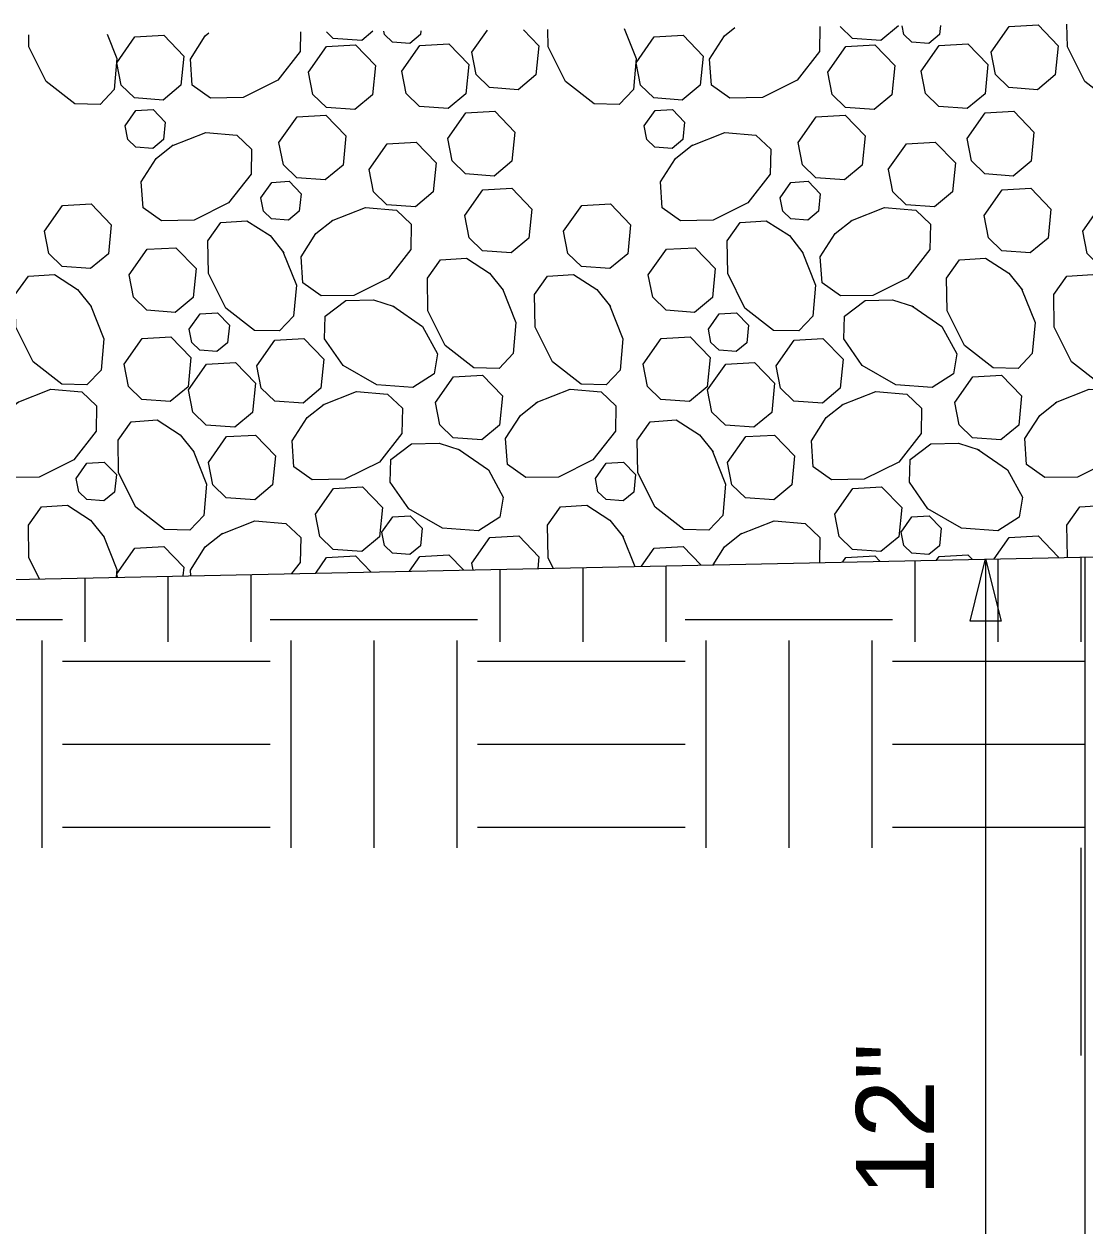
# Model space of a CAD drawing. Extents: x 10368.3 to 10426.8, y 9886.2 to 9938.1.
# Drawn here: x 10376.31 to 10390.52, y 9908.51 to 9924.61 of the extents above; entities that cross this region are included whole.
import ezdxf

# ---------------------------------------------------------------- set-up
doc = ezdxf.new("R2010")
doc.units = 0
for name, color, linetype in [('Default', 7, 'Continuous'), ('G-ANNO-TEXT', 7, 'Continuous'), ('G-DETL-OTLN', 7, 'Continuous'), ('G-DETL-PATT', 7, 'Continuous')]:
    doc.layers.add(name, color=color, linetype=linetype)

# ---------------------------------------------------------------- blocks, each defined once
blk = doc.blocks.new('TERARR')
at = {"layer": 'Default'}
blk.add_lwpolyline([(-0.667, 0.167), (0, 0), (-0.667, -0.167)], close=True, dxfattribs=at)

msp = doc.modelspace()

# ---------------------------------------------------------------- linework, layer by layer
at = {"layer": 'Default'}
for p, q in [((10389.352, 9917.445), (10389.352, 9916.333)), ((10390.464, 9917.469), (10390.464, 9916.333)), ((10390.464, 9913.573), (10390.464, 9910.793))]:
    msp.add_line(p, q, dxfattribs=at)
for points in [[(10388.022, 9924.584), (10387.785, 9924.387), (10387.404, 9924.414), (10387.237, 9924.576)], [(10388.583, 9924.59), (10388.57, 9924.466), (10388.427, 9924.347), (10388.198, 9924.363), (10388.09, 9924.468), (10388.068, 9924.585)], [(10380.98, 9924.511), (10380.831, 9924.387), (10380.449, 9924.414), (10380.357, 9924.504)], [(10381.621, 9924.518), (10381.616, 9924.466), (10381.473, 9924.347), (10381.244, 9924.363), (10381.136, 9924.468), (10381.127, 9924.512)], [(10377.56, 9917.198), (10377.551, 9917.245)]]:
    msp.add_lwpolyline(points, dxfattribs=at)
at = {"layer": 'G-ANNO-TEXT'}
msp.add_line((10389.187, 9917.408), (10389.187, 9902.473), dxfattribs=at)
at = {"layer": 'G-DETL-OTLN'}
for p, q in [((10368.322, 9917.004), (10418.193, 9918.051)), ((10390.518, 9917.47), (10390.518, 9903.473))]:
    msp.add_line(p, q, dxfattribs=at)
at = {"layer": 'G-DETL-PATT'}
for p, q in [((10383.793, 9917.329), (10383.793, 9916.333)), ((10384.905, 9917.352), (10384.905, 9916.333)), ((10388.24, 9917.422), (10388.24, 9916.333)), ((10377.122, 9917.189), (10377.122, 9916.333)), ((10378.233, 9917.212), (10378.233, 9916.333)), ((10379.345, 9917.235), (10379.345, 9916.333)), ((10382.681, 9917.305), (10382.681, 9916.333)), ((10374.043, 9916.63), (10376.823, 9916.63)), ((10379.603, 9916.63), (10382.382, 9916.63)), ((10385.162, 9916.63), (10387.942, 9916.63)), ((10376.545, 9916.352), (10376.545, 9913.573)), ((10379.881, 9916.352), (10379.881, 9913.573)), ((10380.993, 9916.352), (10380.993, 9913.573)), ((10382.104, 9916.352), (10382.104, 9913.573)), ((10385.44, 9916.352), (10385.44, 9913.573)), ((10386.552, 9916.352), (10386.552, 9913.573)), ((10387.664, 9916.352), (10387.664, 9913.573)), ((10376.823, 9916.074), (10379.603, 9916.074)), ((10382.382, 9916.074), (10385.162, 9916.074)), ((10387.942, 9916.074), (10390.518, 9916.074)), ((10376.823, 9914.963), (10379.603, 9914.963)), ((10382.382, 9914.963), (10385.162, 9914.963)), ((10387.942, 9914.963), (10390.518, 9914.963)), ((10376.823, 9913.851), (10379.603, 9913.851)), ((10382.382, 9913.851), (10385.162, 9913.851)), ((10387.942, 9913.851), (10390.518, 9913.851))]:
    msp.add_line(p, q, dxfattribs=at)
for points in [[(10386.967, 9924.573), (10386.961, 9924.239), (10386.661, 9923.856), (10386.197, 9923.624), (10385.76, 9923.616), (10385.514, 9923.791), (10385.491, 9924.139), (10385.691, 9924.45), (10385.83, 9924.561)], [(10389.261, 9924.229), (10389.503, 9924.574), (10389.889, 9924.596), (10390.158, 9924.317), (10390.119, 9923.927), (10389.88, 9923.728), (10389.499, 9923.756), (10389.319, 9923.93), (10389.261, 9924.229)], [(10391.28, 9924.598), (10391.459, 9924.145), (10391.423, 9923.729), (10391.235, 9923.532), (10390.898, 9923.538), (10390.514, 9923.838), (10390.283, 9924.302), (10390.277, 9924.608)], [(10377.42, 9924.474), (10377.551, 9924.145), (10377.515, 9923.729), (10377.327, 9923.532), (10376.989, 9923.538), (10376.606, 9923.838), (10376.374, 9924.302), (10376.371, 9924.463)], [(10377.551, 9924.09), (10377.793, 9924.435), (10378.179, 9924.457), (10378.448, 9924.178), (10378.409, 9923.788), (10378.17, 9923.589), (10377.789, 9923.617), (10377.609, 9923.791), (10377.551, 9924.09)], [(10380.011, 9924.501), (10380.006, 9924.239), (10379.706, 9923.856), (10379.243, 9923.624), (10378.806, 9923.616), (10378.56, 9923.791), (10378.537, 9924.139), (10378.736, 9924.45), (10378.784, 9924.488)], [(10382.306, 9924.229), (10382.515, 9924.527)], [(10382.996, 9924.532), (10383.203, 9924.317), (10383.165, 9923.927), (10382.926, 9923.728), (10382.544, 9923.756), (10382.365, 9923.93), (10382.307, 9924.229)], [(10384.346, 9924.546), (10384.505, 9924.145), (10384.469, 9923.729), (10384.281, 9923.532), (10383.944, 9923.538), (10383.56, 9923.838), (10383.328, 9924.302), (10383.324, 9924.535)], [(10384.505, 9924.09), (10384.747, 9924.435), (10385.134, 9924.457), (10385.402, 9924.178), (10385.363, 9923.788), (10385.125, 9923.589), (10384.743, 9923.617), (10384.564, 9923.791), (10384.505, 9924.09)], [(10380.119, 9923.963), (10380.361, 9924.307), (10380.748, 9924.329), (10381.016, 9924.051), (10380.977, 9923.66), (10380.739, 9923.462), (10380.357, 9923.489), (10380.177, 9923.663), (10380.119, 9923.962)], [(10381.368, 9923.977), (10381.61, 9924.321), (10381.996, 9924.343), (10382.265, 9924.065), (10382.226, 9923.674), (10381.987, 9923.476), (10381.606, 9923.503), (10381.426, 9923.678), (10381.368, 9923.977)], [(10387.073, 9923.963), (10387.315, 9924.307), (10387.702, 9924.329), (10387.97, 9924.051), (10387.932, 9923.66), (10387.693, 9923.462), (10387.311, 9923.489), (10387.132, 9923.663), (10387.074, 9923.962)], [(10388.322, 9923.977), (10388.564, 9924.321), (10388.951, 9924.343), (10389.219, 9924.065), (10389.18, 9923.674), (10388.942, 9923.476), (10388.56, 9923.503), (10388.38, 9923.678), (10388.322, 9923.977)], [(10377.661, 9923.242), (10377.806, 9923.448), (10378.038, 9923.462), (10378.199, 9923.295), (10378.176, 9923.06), (10378.033, 9922.941), (10377.804, 9922.958), (10377.696, 9923.062), (10377.661, 9923.242)], [(10381.984, 9923.073), (10382.226, 9923.417), (10382.612, 9923.439), (10382.881, 9923.161), (10382.842, 9922.771), (10382.603, 9922.572), (10382.222, 9922.6), (10382.042, 9922.774), (10381.984, 9923.073)], [(10384.615, 9923.242), (10384.761, 9923.448), (10384.992, 9923.462), (10385.154, 9923.295), (10385.13, 9923.06), (10384.987, 9922.941), (10384.758, 9922.958), (10384.65, 9923.062), (10384.616, 9923.242)], [(10388.938, 9923.073), (10389.18, 9923.417), (10389.566, 9923.439), (10389.835, 9923.161), (10389.796, 9922.771), (10389.557, 9922.572), (10389.176, 9922.6), (10388.996, 9922.774), (10388.938, 9923.073)], [(10379.722, 9923.021), (10379.964, 9923.365), (10380.35, 9923.387), (10380.619, 9923.109), (10380.58, 9922.718), (10380.342, 9922.52), (10379.96, 9922.548), (10379.781, 9922.722), (10379.722, 9923.021)], [(10386.676, 9923.021), (10386.918, 9923.365), (10387.305, 9923.387), (10387.574, 9923.109), (10387.535, 9922.718), (10387.296, 9922.52), (10386.914, 9922.548), (10386.735, 9922.722), (10386.677, 9923.021)], [(10378.288, 9922.977), (10378.741, 9923.156), (10379.157, 9923.12), (10379.355, 9922.932), (10379.348, 9922.595), (10379.048, 9922.211), (10378.585, 9921.979), (10378.148, 9921.972), (10377.902, 9922.147), (10377.878, 9922.495), (10378.078, 9922.806), (10378.307, 9922.988)], [(10385.243, 9922.977), (10385.695, 9923.156), (10386.111, 9923.12), (10386.309, 9922.932), (10386.303, 9922.595), (10386.002, 9922.211), (10385.539, 9921.979), (10385.102, 9921.972), (10384.856, 9922.147), (10384.833, 9922.495), (10385.032, 9922.806), (10385.261, 9922.988)], [(10380.93, 9922.661), (10381.172, 9923.005), (10381.559, 9923.027), (10381.827, 9922.748), (10381.788, 9922.358), (10381.55, 9922.16), (10381.168, 9922.187), (10380.989, 9922.361), (10380.93, 9922.661)], [(10387.884, 9922.661), (10388.126, 9923.005), (10388.513, 9923.027), (10388.782, 9922.748), (10388.743, 9922.358), (10388.504, 9922.16), (10388.122, 9922.187), (10387.943, 9922.361), (10387.885, 9922.661)], [(10379.48, 9922.281), (10379.625, 9922.487), (10379.857, 9922.501), (10380.018, 9922.333), (10379.995, 9922.099), (10379.852, 9921.98), (10379.623, 9921.997), (10379.515, 9922.101), (10379.48, 9922.281)], [(10386.434, 9922.281), (10386.579, 9922.487), (10386.811, 9922.501), (10386.972, 9922.333), (10386.949, 9922.099), (10386.806, 9921.98), (10386.577, 9921.997), (10386.469, 9922.101), (10386.434, 9922.281)], [(10382.211, 9922.042), (10382.453, 9922.387), (10382.84, 9922.409), (10383.108, 9922.13), (10383.07, 9921.74), (10382.831, 9921.541), (10382.449, 9921.569), (10382.27, 9921.743), (10382.212, 9922.042)], [(10389.166, 9922.042), (10389.408, 9922.387), (10389.794, 9922.409), (10390.063, 9922.13), (10390.024, 9921.74), (10389.785, 9921.541), (10389.404, 9921.569), (10389.224, 9921.743), (10389.166, 9922.042)], [(10376.58, 9921.832), (10376.822, 9922.176), (10377.209, 9922.198), (10377.477, 9921.919), (10377.438, 9921.529), (10377.2, 9921.331), (10376.818, 9921.358), (10376.639, 9921.532), (10376.581, 9921.831)], [(10380.428, 9921.971), (10380.881, 9922.15), (10381.297, 9922.114), (10381.494, 9921.926), (10381.488, 9921.589), (10381.188, 9921.205), (10380.724, 9920.973), (10380.287, 9920.966), (10380.041, 9921.141), (10380.018, 9921.489), (10380.218, 9921.8), (10380.446, 9921.982)], [(10383.535, 9921.832), (10383.777, 9922.176), (10384.163, 9922.198), (10384.432, 9921.919), (10384.393, 9921.529), (10384.154, 9921.331), (10383.773, 9921.358), (10383.593, 9921.532), (10383.535, 9921.831)], [(10387.382, 9921.971), (10387.835, 9922.15), (10388.251, 9922.114), (10388.449, 9921.926), (10388.442, 9921.589), (10388.142, 9921.205), (10387.678, 9920.973), (10387.242, 9920.966), (10386.996, 9921.141), (10386.972, 9921.489), (10387.172, 9921.8), (10387.401, 9921.982)], [(10390.489, 9921.832), (10390.731, 9922.176), (10391.117, 9922.198), (10391.386, 9921.919), (10391.347, 9921.529), (10391.108, 9921.331), (10390.727, 9921.358), (10390.547, 9921.532), (10390.489, 9921.831)], [(10379.775, 9921.563), (10379.955, 9921.11), (10379.919, 9920.694), (10379.731, 9920.497), (10379.393, 9920.503), (10379.01, 9920.803), (10378.778, 9921.267), (10378.77, 9921.704), (10378.945, 9921.95), (10379.293, 9921.973), (10379.605, 9921.773), (10379.787, 9921.545)], [(10386.73, 9921.563), (10386.909, 9921.11), (10386.873, 9920.694), (10386.685, 9920.497), (10386.348, 9920.503), (10385.964, 9920.803), (10385.733, 9921.267), (10385.725, 9921.704), (10385.9, 9921.95), (10386.248, 9921.973), (10386.559, 9921.773), (10386.741, 9921.545)], [(10377.715, 9921.246), (10377.957, 9921.59), (10378.343, 9921.612), (10378.612, 9921.334), (10378.573, 9920.944), (10378.334, 9920.745), (10377.953, 9920.773), (10377.773, 9920.947), (10377.715, 9921.246)], [(10384.669, 9921.246), (10384.911, 9921.59), (10385.297, 9921.612), (10385.566, 9921.334), (10385.527, 9920.944), (10385.289, 9920.745), (10384.907, 9920.773), (10384.728, 9920.947), (10384.669, 9921.246)], [(10382.715, 9921.062), (10382.895, 9920.609), (10382.859, 9920.193), (10382.671, 9919.995), (10382.333, 9920.002), (10381.95, 9920.302), (10381.718, 9920.765), (10381.71, 9921.202), (10381.885, 9921.448), (10382.233, 9921.471), (10382.544, 9921.272), (10382.727, 9921.043)], [(10389.669, 9921.062), (10389.849, 9920.609), (10389.813, 9920.193), (10389.625, 9919.995), (10389.287, 9920.002), (10388.904, 9920.302), (10388.672, 9920.765), (10388.664, 9921.202), (10388.839, 9921.448), (10389.187, 9921.471), (10389.499, 9921.272), (10389.681, 9921.043)], [(10377.196, 9920.842), (10377.375, 9920.389), (10377.339, 9919.973), (10377.151, 9919.776), (10376.814, 9919.782), (10376.43, 9920.082), (10376.199, 9920.546), (10376.191, 9920.983), (10376.366, 9921.229), (10376.714, 9921.252), (10377.025, 9921.052), (10377.207, 9920.824)], [(10384.15, 9920.842), (10384.329, 9920.389), (10384.294, 9919.973), (10384.106, 9919.776), (10383.768, 9919.782), (10383.385, 9920.082), (10383.153, 9920.546), (10383.145, 9920.983), (10383.32, 9921.229), (10383.668, 9921.252), (10383.979, 9921.052), (10384.162, 9920.824)], [(10391.104, 9920.842), (10391.284, 9920.389), (10391.248, 9919.973), (10391.06, 9919.776), (10390.722, 9919.782), (10390.339, 9920.082), (10390.107, 9920.546), (10390.099, 9920.983), (10390.274, 9921.229), (10390.622, 9921.252), (10390.934, 9921.052), (10391.116, 9920.824)], [(10381.246, 9920.833), (10381.647, 9920.556), (10381.847, 9920.19), (10381.801, 9919.921), (10381.516, 9919.739), (10381.031, 9919.776), (10380.581, 9920.033), (10380.332, 9920.392), (10380.341, 9920.694), (10380.618, 9920.906), (10380.987, 9920.913), (10381.266, 9920.824)], [(10388.2, 9920.833), (10388.601, 9920.556), (10388.801, 9920.19), (10388.755, 9919.921), (10388.471, 9919.739), (10387.985, 9919.776), (10387.535, 9920.033), (10387.286, 9920.392), (10387.295, 9920.694), (10387.572, 9920.906), (10387.942, 9920.913), (10388.22, 9920.824)], [(10378.52, 9920.521), (10378.665, 9920.727), (10378.897, 9920.741), (10379.058, 9920.573), (10379.035, 9920.339), (10378.892, 9920.22), (10378.663, 9920.237), (10378.555, 9920.341), (10378.52, 9920.521)], [(10385.474, 9920.521), (10385.619, 9920.727), (10385.851, 9920.741), (10386.012, 9920.573), (10385.989, 9920.339), (10385.846, 9920.22), (10385.617, 9920.237), (10385.509, 9920.341), (10385.474, 9920.521)], [(10377.647, 9920.051), (10377.889, 9920.395), (10378.275, 9920.417), (10378.544, 9920.139), (10378.505, 9919.748), (10378.266, 9919.55), (10377.885, 9919.577), (10377.705, 9919.751), (10377.647, 9920.051)], [(10379.427, 9920.03), (10379.669, 9920.374), (10380.055, 9920.396), (10380.324, 9920.118), (10380.285, 9919.728), (10380.046, 9919.529), (10379.665, 9919.557), (10379.485, 9919.731), (10379.427, 9920.03)], [(10384.601, 9920.051), (10384.843, 9920.395), (10385.23, 9920.417), (10385.498, 9920.139), (10385.459, 9919.748), (10385.221, 9919.55), (10384.839, 9919.577), (10384.66, 9919.751), (10384.602, 9920.051)], [(10386.381, 9920.03), (10386.623, 9920.374), (10387.009, 9920.396), (10387.278, 9920.118), (10387.239, 9919.728), (10387.001, 9919.529), (10386.619, 9919.557), (10386.439, 9919.731), (10386.381, 9920.03)], [(10378.51, 9919.709), (10378.752, 9920.053), (10379.138, 9920.075), (10379.407, 9919.797), (10379.368, 9919.406), (10379.129, 9919.208), (10378.748, 9919.236), (10378.568, 9919.41), (10378.51, 9919.709)], [(10385.464, 9919.709), (10385.706, 9920.053), (10386.092, 9920.075), (10386.361, 9919.797), (10386.322, 9919.406), (10386.083, 9919.208), (10385.702, 9919.236), (10385.522, 9919.41), (10385.464, 9919.709)], [(10381.819, 9919.538), (10382.061, 9919.883), (10382.447, 9919.905), (10382.716, 9919.626), (10382.677, 9919.236), (10382.438, 9919.037), (10382.057, 9919.065), (10381.877, 9919.239), (10381.819, 9919.538)], [(10388.773, 9919.538), (10389.015, 9919.883), (10389.401, 9919.905), (10389.67, 9919.626), (10389.631, 9919.236), (10389.392, 9919.037), (10389.011, 9919.065), (10388.832, 9919.239), (10388.773, 9919.538)], [(10376.214, 9919.537), (10376.667, 9919.716), (10377.083, 9919.68), (10377.28, 9919.492), (10377.274, 9919.155), (10376.974, 9918.771), (10376.51, 9918.539), (10376.073, 9918.532), (10375.827, 9918.707), (10375.804, 9919.055), (10376.004, 9919.366), (10376.232, 9919.548)], [(10380.309, 9919.507), (10380.761, 9919.686), (10381.177, 9919.65), (10381.375, 9919.462), (10381.369, 9919.125), (10381.069, 9918.741), (10380.605, 9918.51), (10380.168, 9918.502), (10379.922, 9918.677), (10379.899, 9919.025), (10380.098, 9919.336), (10380.327, 9919.518)], [(10383.168, 9919.537), (10383.621, 9919.716), (10384.037, 9919.68), (10384.235, 9919.492), (10384.228, 9919.155), (10383.928, 9918.771), (10383.465, 9918.539), (10383.028, 9918.532), (10382.782, 9918.707), (10382.758, 9919.055), (10382.958, 9919.366), (10383.187, 9919.548)], [(10387.263, 9919.507), (10387.716, 9919.686), (10388.132, 9919.65), (10388.329, 9919.462), (10388.323, 9919.125), (10388.023, 9918.741), (10387.559, 9918.51), (10387.122, 9918.502), (10386.876, 9918.677), (10386.853, 9919.025), (10387.053, 9919.336), (10387.281, 9919.518)], [(10390.123, 9919.537), (10390.575, 9919.716), (10390.991, 9919.68), (10391.189, 9919.492), (10391.183, 9919.155), (10390.882, 9918.771), (10390.419, 9918.539), (10389.982, 9918.532), (10389.736, 9918.707), (10389.713, 9919.055), (10389.912, 9919.366), (10390.141, 9919.548)], [(10378.572, 9918.895), (10378.751, 9918.442), (10378.715, 9918.026), (10378.527, 9917.828), (10378.19, 9917.835), (10377.806, 9918.135), (10377.575, 9918.598), (10377.567, 9919.035), (10377.742, 9919.281), (10378.09, 9919.305), (10378.401, 9919.105), (10378.583, 9918.876)], [(10385.526, 9918.895), (10385.705, 9918.442), (10385.669, 9918.026), (10385.482, 9917.828), (10385.144, 9917.835), (10384.76, 9918.135), (10384.529, 9918.598), (10384.521, 9919.035), (10384.696, 9919.281), (10385.044, 9919.305), (10385.355, 9919.105), (10385.538, 9918.876)], [(10378.777, 9918.736), (10379.019, 9919.081), (10379.406, 9919.102), (10379.674, 9918.824), (10379.636, 9918.434), (10379.397, 9918.235), (10379.015, 9918.263), (10378.836, 9918.437), (10378.777, 9918.736)], [(10385.732, 9918.736), (10385.974, 9919.081), (10386.36, 9919.102), (10386.629, 9918.824), (10386.59, 9918.434), (10386.351, 9918.235), (10385.97, 9918.263), (10385.79, 9918.437), (10385.732, 9918.736)], [(10382.126, 9918.913), (10382.527, 9918.636), (10382.727, 9918.27), (10382.681, 9918.001), (10382.396, 9917.819), (10381.911, 9917.856), (10381.461, 9918.113), (10381.212, 9918.472), (10381.221, 9918.774), (10381.498, 9918.986), (10381.867, 9918.993), (10382.146, 9918.904)], [(10389.08, 9918.913), (10389.481, 9918.636), (10389.681, 9918.27), (10389.635, 9918.001), (10389.351, 9917.819), (10388.865, 9917.856), (10388.415, 9918.113), (10388.166, 9918.472), (10388.175, 9918.774), (10388.452, 9918.986), (10388.822, 9918.993), (10389.1, 9918.904)], [(10377.005, 9918.521), (10377.151, 9918.727), (10377.382, 9918.741), (10377.544, 9918.573), (10377.52, 9918.339), (10377.377, 9918.22), (10377.148, 9918.237), (10377.04, 9918.341), (10377.006, 9918.521)], [(10383.96, 9918.521), (10384.105, 9918.727), (10384.337, 9918.741), (10384.498, 9918.573), (10384.475, 9918.339), (10384.332, 9918.22), (10384.103, 9918.237), (10383.995, 9918.341), (10383.96, 9918.521)], [(10380.211, 9918.042), (10380.453, 9918.387), (10380.84, 9918.409), (10381.108, 9918.13), (10381.07, 9917.74), (10380.831, 9917.541), (10380.449, 9917.569), (10380.27, 9917.743), (10380.212, 9918.042)], [(10387.166, 9918.042), (10387.408, 9918.387), (10387.794, 9918.409), (10388.063, 9918.13), (10388.024, 9917.74), (10387.785, 9917.541), (10387.404, 9917.569), (10387.224, 9917.743), (10387.166, 9918.042)], [(10376.514, 9917.176), (10376.374, 9917.456), (10376.366, 9917.893), (10376.541, 9918.139), (10376.889, 9918.163), (10377.2, 9917.963), (10377.383, 9917.734)], [(10383.396, 9917.32), (10383.328, 9917.456), (10383.321, 9917.893), (10383.495, 9918.139), (10383.844, 9918.163), (10384.155, 9917.963), (10384.337, 9917.734)], [(10390.282, 9917.465), (10390.275, 9917.893), (10390.45, 9918.139), (10390.798, 9918.163), (10391.109, 9917.963), (10391.291, 9917.734)], [(10378.946, 9917.776), (10379.399, 9917.955), (10379.815, 9917.919), (10380.013, 9917.731), (10380.006, 9917.394), (10379.891, 9917.247)], [(10381.101, 9917.802), (10381.246, 9918.008), (10381.478, 9918.022), (10381.639, 9917.855), (10381.616, 9917.62), (10381.473, 9917.501), (10381.244, 9917.518), (10381.136, 9917.622), (10381.101, 9917.802)], [(10385.901, 9917.776), (10386.354, 9917.955), (10386.769, 9917.919), (10386.967, 9917.731), (10386.961, 9917.395)], [(10388.055, 9917.802), (10388.201, 9918.008), (10388.432, 9918.022), (10388.594, 9917.855), (10388.57, 9917.62), (10388.427, 9917.501), (10388.198, 9917.518), (10388.09, 9917.622), (10388.056, 9917.802)], [(10377.371, 9917.753), (10377.551, 9917.3), (10377.542, 9917.197)], [(10378.542, 9917.218), (10378.537, 9917.294), (10378.736, 9917.605), (10378.965, 9917.787)], [(10382.306, 9917.384), (10382.548, 9917.728), (10382.935, 9917.75), (10383.203, 9917.472), (10383.188, 9917.316)], [(10384.325, 9917.753), (10384.488, 9917.343)], [(10385.537, 9917.365), (10385.691, 9917.605), (10385.919, 9917.787)], [(10389.303, 9917.444), (10389.503, 9917.728), (10389.889, 9917.75), (10390.158, 9917.472), (10390.157, 9917.462)], [(10377.551, 9917.245), (10377.793, 9917.589), (10378.179, 9917.611), (10378.448, 9917.333), (10378.436, 9917.216)], [(10380.215, 9917.254), (10380.361, 9917.461), (10380.748, 9917.484), (10380.954, 9917.269)], [(10381.472, 9917.28), (10381.61, 9917.476), (10381.996, 9917.498), (10382.192, 9917.295)], [(10384.576, 9917.345), (10384.747, 9917.589), (10385.134, 9917.611), (10385.374, 9917.362)], [(10387.273, 9917.402), (10387.315, 9917.461), (10387.702, 9917.484), (10387.771, 9917.412)], [(10388.531, 9917.428), (10388.564, 9917.476), (10388.951, 9917.498), (10389.008, 9917.438)], [(10382.323, 9917.298), (10382.307, 9917.384)]]:
    msp.add_lwpolyline(points, dxfattribs=at)

# ---------------------------------------------------------------- block references
at = {"layer": 'G-ANNO-TEXT', "xscale": 1.24992, "yscale": 1.24992, "rotation": 90}
msp.add_blockref('TERARR', (10389.187, 9917.442), dxfattribs=at)

# ---------------------------------------------------------------- texts
at = {"layer": 'G-ANNO-TEXT'}
msp.add_text('12"', height=1.044, rotation=90, dxfattribs=at).set_placement((10388.496, 9908.91))

doc.saveas('drawing.dxf')
